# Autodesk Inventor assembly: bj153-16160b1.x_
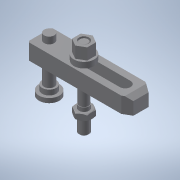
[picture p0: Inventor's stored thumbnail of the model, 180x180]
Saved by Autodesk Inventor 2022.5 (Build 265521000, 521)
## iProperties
Part Number: bj153-16160b1.x_
Material: 一般
Document SubType Name: Assembly
Designer: ImaoCorp
Sending System: SOLIDWORKS 2017-2017317
MC: AMD64
MC_MODEL: Intel64 Family 6 Model 60 Stepping 3, GenuineIntel
OS: Windows_NT
FRU: Parasolid Version 29.0, build 201,  4-17-2017
FORMAT: text
GUISE: transmit
KEY: bj153-16160b1
FILE: bj153-16160b1.x_t
DATE: Fri Mar 15 10:22:53 2019
Author: ImaoCorp
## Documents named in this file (6)
- X:\14_SW2022-Inv2022\00_全2023-1023新製品(TCC)まで\b\bj153-16160b1\BJ153-16160B1.iam
- X:\14_SW2022-Inv2022\00_全2023-1023新製品(TCC)まで\b\bj153-16160b1\bj153-16160b1_01.ipt
- X:\14_SW2022-Inv2022\00_全2023-1023新製品(TCC)まで\b\bj153-16160b1\bj153-16160b1_02.ipt
- X:\14_SW2022-Inv2022\00_全2023-1023新製品(TCC)まで\b\bj153-16160b1\bj153-16160b1_03.ipt
- X:\14_SW2022-Inv2022\00_全2023-1023新製品(TCC)まで\b\bj153-16160b1\bj153-16160b1_04.ipt
- X:\14_SW2022-Inv2022\00_全2023-1023新製品(TCC)まで\b\bj153-16160b1\bj153-16160b1_05.ipt
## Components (5 placed, 5 different names)
1. bj153-16160b1_01
2. bj153-16160b1_02
3. bj153-16160b1_03
4. bj153-16160b1_04
5. bj153-16160b1_05
